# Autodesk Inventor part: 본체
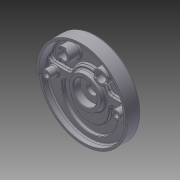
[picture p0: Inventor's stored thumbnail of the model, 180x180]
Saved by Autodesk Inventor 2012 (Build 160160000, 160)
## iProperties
Created: 2015-04
Part Number: 본체
Material: 알루미늄-6061
Document SubType Name: Modeling
Designer: Owner
Density: 2.71 g/cm^3
Mass: 1049.41 g
Surface Area: 1028.3 cm^2
Volume: 387.235 cm^3
Author: Owner
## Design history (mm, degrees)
sketch "스케치1"
  geometry: C1 r 95 at (0, 0); 1 further point
  constraints: 1 centre point, 1 coincident
  dimensions: "d0" = 190 diameter of C1
extrude "돌출1" new body sketch "스케치1" distance "d1" = 27; taper "d2" = 0 deg
sketch "스케치2"
  geometry: L1 (-95, 0)-(95, 0); L2 (-94.638, -8.28)-(-89.658, -7.844); L3 (89.658, -7.844)-(94.638, -8.28); A1 r 95 centre (0, 0) between (-95, 0) and (95, 0) reference; A2 r 95 centre (0, 0) between (94.638, -8.28) and (-94.638, -8.28); A3 r 90 centre (0, 0) between (89.658, -7.844) and (-89.658, -7.844); 1 further point
  constraints: 10 point on circle, 6 end point, 3 coincident, 2 centre point, 1 concentric, 1 horizontal, 1 midpoint
  dimensions: "d3" = 180 diameter of A3; "d6" = 5 deg angle of L1 L2; "d8" = 5 deg angle of L1 L3; "d9" = 16.49658 distance from line of L3.end L2; "d10" = 15.62834 distance from line of L3.start L2
extrude "돌출2" join sketch "스케치2" distance "d11" = 5; taper "d12" = 0 deg
sketch "스케치3"
  geometry: C1 r 90 at (0, 0); A1 r 95 centre (0, 0) between (-94.638, -8.28) and (94.638, -8.28) reference
  constraints: 1 centre point, 1 coincident
  dimensions: "d13" = 180 diameter of C1
extrude "돌출3" cut sketch "스케치3" distance "d14" = 20; taper "d15" = 0 deg
sketch "스케치4"
  geometry: L1 (-89.196, 12)-(89.196, 12); C1 r 42 at (0, 0); A1 r 90 centre (0, 0) between (-89.196, 12) and (89.196, 12) reference
  constraints: 2 end point, 2 point on circle, 1 centre point, 1 coincident, 1 horizontal
  dimensions: "d16" = 84 diameter of C1; "d17" = 12 distance from line of L1 C1.centre
extrude "돌출4" join sketch "스케치4" distance "d18" = 7; taper "d19" = 0 deg
fillet "모깎기1" dims "d20" = 10
sketch "스케치5"
  geometry: L1 (-90, 14)-(24.75, 14) reference; L2 (90, 32)-(-7.844, 32) reference; L3 (35, 14)-(33.237, 24); L4 (33.237, 24)-(0, 24); L5 (0, 14)-(0, 24); L6 (17.769, 14)-(42, 14) reference; L7 (0, 14)-(35, 14); 1 further point
  constraints: 8 end point, 2 point on line, 1 collinear, 1 parallel, 1 vertical, 1 vertical alignment
  dimensions: "d21" = 35 distance of L3.start L5.start; "d22" = 10 distance between parallel lines of L4 L1; "d23" = 100 deg angle of L6 L3
revolve "회전1" sketch "스케치5" stored, may be unused: angle "d24" = 90 deg
hole "구멍1" diameter "d27" = 23; stored, may be unused: countersink angle "d31" = 90 deg, drill point angle "d33" = 118 deg; dims "d25" = 10, "d26" = 10, "d28" = 6, "d29" = 50, "d30" = 15, "d32" = 8
sketch "스케치6"
  geometry: C1 r 15 at (-40, 52); C2 r 15 at (40, 52); A1 r 90 centre (0, 0) between (86.53, 24.75) and (-86.53, 24.75) reference
  constraints: 2 centre point, 1 horizontal alignment
  dimensions: "d34" = 30 diameter of C1; "d35" = 30 diameter of C2; "d36" = 80 distance of C1.centre C2.centre; "d37" = 40 horizontal distance of C1.centre A1.centre; "d38" = 52 vertical distance of C1.centre A1.centre
extrude "돌출5" join sketch "스케치6" distance "d39" = 25; taper "d40" = 0 deg
hole "구멍2" diameter "d43" = 20; stored, may be unused: countersink angle "d47" = 90 deg, drill point angle "d49" = 118 deg; dims "d41" = 10, "d42" = 10, "d44" = 6, "d45" = 4, "d46" = 2, "d48" = 8
hole "구멍3" diameter "d52" = 20; stored, may be unused: countersink angle "d56" = 90 deg, drill point angle "d58" = 118 deg; dims "d50" = 10, "d51" = 10, "d53" = 6, "d54" = 4, "d55" = 2, "d57" = 8
sketch "스케치7"
  geometry: L1 (-6, 16.78)-(6, 16.78); L2 (6, 16.78)-(6, -16.78); L3 (6, -16.78)-(-6, -16.78); L4 (-6, -16.78)-(-6, 16.78); C1 r 10 at (0, 0) reference; 3 further points
  constraints: 8 end point, 2 midpoint, 2 parallel, 1 horizontal, 1 horizontal alignment, 1 perpendicular, 1 vertical alignment
  dimensions: "d59" = 12 distance of L1.start L1.end
extrude "돌출6" cut sketch "스케치7" distance "d60" = 3; taper "d61" = 0 deg
sketch "스케치8"
  geometry: L1 (-26.553, 6)-(26.553, 6); L2 (26.553, 6)-(26.553, -6); L3 (26.553, -6)-(-26.553, -6); L4 (-26.553, -6)-(-26.553, 6); C1 r 10 at (0, 0) reference; 3 further points
  constraints: 8 end point, 2 midpoint, 2 parallel, 1 horizontal, 1 horizontal alignment, 1 perpendicular, 1 vertical alignment
  dimensions: "d62" = 12 distance of L3.end L1.start
extrude "돌출7" cut sketch "스케치8" distance "d63" = 3; taper "d64" = 0 deg
sketch "스케치9"
  geometry: L1 (-76.916, 12)-(-47.117, 12) reference; L2 (47.117, 12)-(76.916, 12) reference; L3 (-59, -19)-(59, -19); L4 (-58.749, -14)-(58.749, -14); L5 (0, 0)-(0, -57.638); A1 r 35 centre (0, 0) between (34.911, 2.5) and (-34.911, 2.5) reference; A2 r 42 centre (0, 0) between (38.056, 17.769) and (-38.056, 17.769) reference; A3 r 50 centre (0, -19) between (-49.749, -14) and (49.749, -14); A4 r 9 centre (-49.749, -14) between (-58.749, -14) and (-58.704, -13.1); A5 r 9 centre (49.749, -14) between (58.749, -14) and (58.704, -13.1); A6 r 59 centre (0, -19) between (50.2, 12) and (-50.2, 12); A7 r 59 centre (0, -19) between (-58.704, -13.1) and (58.704, -13.1); A8 r 41 centre (0, -19) between (34.911, 2.5) and (-34.911, 2.5); A9 r 41 centre (0, -19) between (-40.794, -14.9) and (40.794, -14.9)
  constraints: 20 point on circle, 7 centre point, 6 end point, 5 point on line, 2 coincident, 2 parallel, 2 tangent, 1 midpoint, 1 vertical
  dimensions: "d68" = 19 distance from line of A1.centre L3; "d69" = 5 distance between parallel lines of L4 L3; "d76" = 18 diameter of A4; "d77" = 18 diameter of A5; "d78" = 59 radius of A7
extrude "돌출8" cut sketch "스케치9" distance "d79" = 7; taper "d80" = 0 deg
sketch "스케치10"
  geometry: L1 (47.117, 12)-(76.916, 12) reference; L2 (-74, 0)-(74, 0); C1 r 35 at (0, 0) reference; C2 r 9 at (-74, 0); C3 r 9 at (74, 0); A1 r 42 centre (0, 0) between (38.056, 17.769) and (-38.056, 17.769) reference; A2 r 74 centre (0, 0) between (-74, 0) and (74, 0); 1 further point
  constraints: 4 coincident, 3 centre point, 2 end point, 2 point on circle, 1 midpoint, 1 parallel
  dimensions: "d81" = 148 diameter of A2; "d82" = 18 diameter of C2; "d83" = 18 diameter of C3
extrude "돌출9" join sketch "스케치10" distance "d84" = 18; taper "d85" = 0 deg
hole "구멍4" diameter "d88" = 11; stored, may be unused: countersink angle "d92" = 90 deg, drill point angle "d94" = 118 deg; dims "d86" = 10, "d87" = 10, "d89" = 6, "d90" = 4, "d91" = 2, "d93" = 8
hole "구멍5" diameter "d97" = 11; stored, may be unused: countersink angle "d101" = 90 deg, drill point angle "d103" = 118 deg; dims "d95" = 10, "d96" = 10, "d98" = 6, "d99" = 4, "d100" = 2, "d102" = 8
hole "구멍6" diameter "d106" = 18; stored, may be unused: countersink angle "d110" = 90 deg, drill point angle "d112" = 0 deg; dims "d104" = 10, "d105" = 10, "d107" = 6, "d108" = 4, "d109" = 2, "d111" = 11
hole "구멍7" diameter "d115" = 18; stored, may be unused: countersink angle "d119" = 90 deg, drill point angle "d121" = 0 deg; dims "d113" = 10, "d114" = 10, "d116" = 6, "d117" = 4, "d118" = 2, "d120" = 11
sketch "스케치11"
  geometry: L1 (0, 0)-(0, -72); L2 (0, 0)-(8.132, -8.132); L3 (39.44, -39.44)-(47.244, -47.244); L4 (0, 0)-(-8.132, -8.132); L5 (-39.44, -39.44)-(-47.244, -47.244); C1 r 95 at (0, 0) reference; C2 r 68 at (0, 0); A1 r 11.5 centre (0, 0) between (8.132, -8.132) and (-8.132, -8.132) reference; A2 r 51 centre (0, 0) between (-32.699, -39.138) and (32.699, -39.138); A3 r 72 centre (0, 0) between (71.48, -8.64) and (-71.48, -8.64); A4 r 72 centre (0, 0) between (-46.97, -54.569) and (46.97, -54.569); A5 r 5 centre (35.904, -42.975) between (39.44, -39.44) and (32.699, -39.138); A6 r 5 centre (43.709, -50.78) between (46.97, -54.569) and (47.244, -47.244); A7 r 5 centre (-43.709, -50.78) between (-47.244, -47.244) and (-46.97, -54.569); A8 r 5 centre (-35.904, -42.975) between (-32.699, -39.138) and (-39.44, -39.44); 6 further points
  constraints: 21 point on circle, 10 end point, 8 centre point, 8 tangent, 4 point on line, 3 coincident, 3 equal radius, 1 vertical, 5 other
  dimensions: "d122" = 102 diameter of A2; "d126" = 72 radius of A4; "d127" = 45 deg angle of L5 L1; "d128" = 45 deg angle of L1 L3; "d129" = 72 distance from line of point (50.912, -50.912) L5; "d130" = 51 distance from line of point (36.062, -36.062) L5; "d131" = 5 radius of A5; "d133" = 136 diameter of C2
extrude "돌출10" join sketch "스케치11" distance "d134" = 5; taper "d135" = 0 deg
sketch "스케치12"
  geometry: C1 r 68 at (0, 0); A1 r 51 centre (0, 0) between (-32.699, -39.138) and (32.699, -39.138) reference
  constraints: 1 centre point, 1 coincident, 1 other
  dimensions: "d136" = 136 diameter of C1
feature "엠보싱1" sketch "스케치12" dims "d137" = 0.5, "d138" = 0
fillet "모깎기2" dims "d139" = 1
fillet "모깎기3" dims "d140" = 3
chamfer "모따기1" distance "d141" = 1; stored, may be unused: second distance "d142" = 2, angle "d143" = 45 deg
node "솔리드1"
other parameters: "d73" = 118, "d74" = 82, "d75" = 9, "d123" = 144, "d124" = 45 deg, "d125" = 45 deg
